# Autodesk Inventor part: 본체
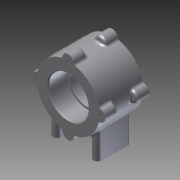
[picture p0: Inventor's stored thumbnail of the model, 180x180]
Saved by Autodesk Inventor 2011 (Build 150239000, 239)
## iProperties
Created: 2015-03
Part Number: 본체
Document SubType Name: Modeling
Designer: Administrator
Density: 1 g/cm^3
Author: Administrator
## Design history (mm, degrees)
sketch "스케치1"
  geometry: L1 (24, -20)-(24, 20) reference; L2 (-24, 20)-(-24, -20) reference; L3 (29, -15)-(29, 15); L4 (19, -15)-(19, 15); L5 (-19, 15)-(-19, -15); L6 (-29, 15)-(-29, -15); L7 (24, -20)-(24, -20); L8 (-24, -20)-(-24, -20); L9 (-24, 20)-(-24, 20); L10 (24, 20)-(24, 20); A1 r 5 centre (-24, 15) between (-24, 20) and (-29, 15); A2 r 5 centre (-24, 15) between (-19, 15) and (-24, 20); A3 r 5 centre (-24, -15) between (-29, -15) and (-24, -20); A4 r 5 centre (-24, -15) between (-24, -20) and (-19, -15); A5 r 5 centre (24, -15) between (19, -15) and (24, -20); A6 r 5 centre (24, -15) between (24, -20) and (29, -15); A7 r 5 centre (24, 15) between (29, 15) and (24, 20); A8 r 5 centre (24, 15) between (24, 20) and (19, 15); 3 further points
  constraints: 20 end point, 16 point on circle, 16 tangent, 9 parallel, 8 centre point, 7 equal radius, 2 perpendicular, 2 vertical, 1 horizontal alignment, 1 midpoint, 1 vertical alignment
  dimensions: "d2" = 5 distance between parallel lines of L1 L4; "d3" = 5 distance between parallel lines of L3 L1; "d4" = 5 distance between parallel lines of L2 L6; "d5" = 5 distance between parallel lines of L5 L2; "d6" = 5 radius of A1
extrude "돌출1" new body sketch "스케치1" distance "d7" = 56; taper "d8" = 0 deg
sketch "스케치2"
  geometry: L1 (15, 56)-(-15, 56) reference; L2 (-15, 0)-(-15, 56) reference; L3 (15, 0)-(-15, 0) reference; L4 (15, 0)-(15, 56) reference; L5 (0, 56)-(-26, 56); L6 (-26, 56)-(-26, 93); L7 (-26, 93)-(26, 93); L8 (26, 93)-(26, 56); L9 (26, 56)-(0, 56); 1 further point
  constraints: 10 end point, 2 point on line, 1 collinear, 1 midpoint, 1 parallel, 1 perpendicular
revolve "회전1" sketch "스케치2" stored, may be unused: angle "d9" = 90 deg
sketch "스케치3"
  geometry: C1 r 37 at (0, 0) reference; C2 r 23.5 at (0, 0); 1 further point
  constraints: 1 centre point, 1 coincident
extrude "돌출2" cut sketch "스케치3" distance "d10" = 22; taper "d11" = 0 deg
sketch "스케치4"
  geometry: C1 r 37 at (0, 0) reference; C2 r 23.5 at (0, 0); 1 further point
  constraints: 1 centre point, 1 coincident
extrude "돌출3" cut sketch "스케치4" distance "d12" = 22; taper "d13" = 0 deg
sketch "스케치5"
  geometry: C1 r 23.5 at (0, 0) reference; C2 r 21 at (0, 0); 1 further point
  constraints: 1 centre point, 1 coincident
extrude "돌출4" cut sketch "스케치5" stored distance "d14" = 22; taper "d15" = 0 deg
fillet "모깎기1" dims "d16" = 3
sketch "스케치6"
  geometry: A1 r 7 centre (0, 37) between (6.969, 36.338) and (-6.969, 36.338); A2 r 7 centre (-37, 0) between (-36.338, 6.969) and (-36.338, -6.969); A3 r 7 centre (0, -37) between (-6.969, -36.338) and (6.969, -36.338); A4 r 7 centre (37, 0) between (36.338, -6.969) and (36.338, 6.969); 2 further points
  constraints: 8 point on circle, 4 centre point, 13 other
extrude "돌출5" join sketch "스케치6" distance "d17" = 15; taper "d18" = 0 deg
fillet "모깎기2" dims "d19" = 3
fillet "모깎기3" dims "d20" = 3
chamfer "모따기1" distance "d21" = 1; stored, may be unused: second distance "d22" = 2, angle "d23" = 45 deg
fillet "모깎기4" dims "d24" = 0.3
sketch "스케치7"
  geometry: A1 r 7 centre (-37, 37) between (-38.239, 43.889) and (-38.239, 30.111) reference; A2 r 7 centre (0, 0) between (-6.889, -1.239) and (6.889, -1.239) reference; A3 r 7 centre (37, 37) between (38.239, 30.111) and (38.239, 43.889) reference; A4 r 7 centre (0, 74) between (6.889, 75.239) and (-6.889, 75.239) reference; 5 further points
  constraints: 4 coincident
hole "Hole1" sketch "스케치7" at (0, 74), (-37, 37), (0, 0), (37, 37) diameter "d25" = 3.242; stored, may be unused: countersink angle "d29" = 90 deg, drill point angle "d31" = 118 deg; dims "d26" = 8, "d27" = 4, "d28" = 2, "d30" = 11
sketch "스케치8"
  geometry: A1 r 7 centre (37, -37) between (38.239, -43.889) and (38.239, -30.111) reference; A2 r 7 centre (0, 0) between (6.889, 1.239) and (-6.889, 1.239) reference; A3 r 7 centre (-37, -37) between (-38.239, -30.111) and (-38.239, -43.889) reference; A4 r 7 centre (0, -74) between (-6.889, -75.239) and (6.889, -75.239) reference; 5 further points
  constraints: 4 coincident
hole "Hole2" sketch "스케치8" at (0, 0), (-37, -37), (0, -74), (37, -37) diameter "d32" = 3.242; stored, may be unused: countersink angle "d36" = 90 deg, drill point angle "d38" = 118 deg; dims "d33" = 8, "d34" = 4, "d35" = 2, "d37" = 11
sketch "스케치9"
  geometry: L1 (-19, -15)-(-19, 15) reference; L2 (-29, 15)-(-29, -15) reference; A1 r 5 centre (24, 15) between (29, 15) and (19, 15) reference; A2 r 5 centre (24, -15) between (19, -15) and (29, -15) reference; A3 r 5 centre (-24, 15) between (-19, 15) and (-29, 15) reference; A4 r 5 centre (-24, -15) between (-29, -15) and (-19, -15) reference; 5 further points
  constraints: 4 coincident
hole "Hole3" sketch "스케치9" at (-24, 15), (-24, -15), (24, -15), (24, 15) diameter "d39" = 4.134; stored, may be unused: countersink angle "d43" = 90 deg, drill point angle "d45" = 118 deg; dims "d40" = 6, "d41" = 4, "d42" = 2, "d44" = 8
node "작업 평면2"
  node "작업 평면1"
sketch "스케치10"
  geometry: L1 (-20.388, 2.814)-(21.091, 2.814); L2 (21.091, 2.814)-(21.091, -3.19); L3 (21.091, -3.19)-(-20.388, -3.19); L4 (-20.388, -3.19)-(-20.388, 2.814); L5 (-26, 18.921)-(-26, -18.921) reference; L6 (-26, 0)-(0, 0); 1 further point
  constraints: 2 end point, 1 midpoint, 1 perpendicular, 2 other
feature "엠보싱1" sketch "스케치10" dims "d2" = 5, "d3" = 5, "d4" = 5, "d5" = 5, "d6" = 5, "d47" = 0.5, "d48" = 0
node "솔리드1"
mirror "대칭1"
node "투영된 루프1"
node "투영된 루프2"
node "작업축1"
other parameters: "d46" = 45 deg
